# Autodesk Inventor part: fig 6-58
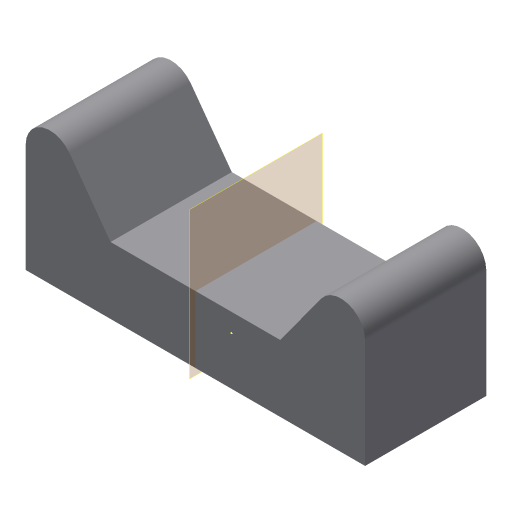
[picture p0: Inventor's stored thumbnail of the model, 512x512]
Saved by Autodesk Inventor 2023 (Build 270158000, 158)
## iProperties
Created: 2011-07
Part Number: fig 6-58
Material: Generic
Document SubType Name: Modeling
Designer: CadCim
Density: 1 g/cm^3
Appearance: Default
Author: CadCim
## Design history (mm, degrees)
sketch "Sketch1"
  geometry: 1 further point
sketch "Sketch2"
  geometry: L1 (3, -4)-(17, -4); L2 (17, -4)-(17, 7); L3 (17, 7)-(14, 7); L4 (14, 7)-(10, 1.5); L5 (10, 1.5)-(3, 1.5); L6 (3, -4)-(-11, -4); L7 (-11, -4)-(-11, 7); L8 (-11, 7)-(-8, 7); L9 (-8, 7)-(-4, 1.5); L10 (-4, 1.5)-(3, 1.5); 1 further point
  constraints: 20 end point, 2 parallel, 1 perpendicular
extrude "Extrusion1" new body sketch "Sketch2" distance "d0" = 10; taper "d1" = 0 deg
fillet "Fillet1" dims "d2" = 2
workplane "Work Plane1"
mirror "Mirror1"
body "Solid1"
